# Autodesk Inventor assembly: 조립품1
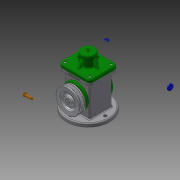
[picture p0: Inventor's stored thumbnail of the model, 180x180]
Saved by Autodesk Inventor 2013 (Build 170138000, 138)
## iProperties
Created: 2018-10
Part Number: 조립품1
Document SubType Name: Assembly
Designer: Administrator
Author: Administrator
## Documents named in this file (18)
- C:\Users\Administrator\Desktop\481007V1006\조립품1.iam
- C:\Users\Administrator\Desktop\481007V1006\본체1.ipt
- C:\Users\Administrator\Desktop\481007V1006\볼트 M4 x 8.ipt
- C:\Users\Administrator\Desktop\481007V1006\볼트 M4 x 10.ipt
- C:\Users\Administrator\Desktop\481007V1006\슬라이더.ipt
- C:\Users\Administrator\Desktop\481007V1006\앞커버.ipt
- C:\Users\Administrator\Desktop\481007V1006\오일 실 17 30 8.ipt
- C:\Users\Administrator\Desktop\481007V1006\와셔 4x16.ipt
- C:\Users\Administrator\Desktop\481007V1006\클레비스 핀 6 x 22.ipt
- 클레비스 핀 6 x 22.ipt
- C:\Users\Administrator\Desktop\481007V1006\키 4 x 4 x 12.ipt
- C:\Users\Administrator\Desktop\481007V1006\편심축.ipt
- C:\Users\Administrator\Desktop\481007V1006\E-링.ipt
- C:\Users\Administrator\Desktop\481007V1006\V-벨트풀리.ipt
- C:\Users\Administrator\Desktop\481007V1006\덮개.ipt
- C:\Users\Administrator\Desktop\481007V1006\뒤커버.ipt
- C:\Users\Administrator\Desktop\481007V1006\링크.ipt
- C:\Users\Administrator\Desktop\481007V1006\베어링 17 x 40 x 12.ipt
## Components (2 placed, 2 different names)
1. E-링:1
2. V-벨트풀리:1
